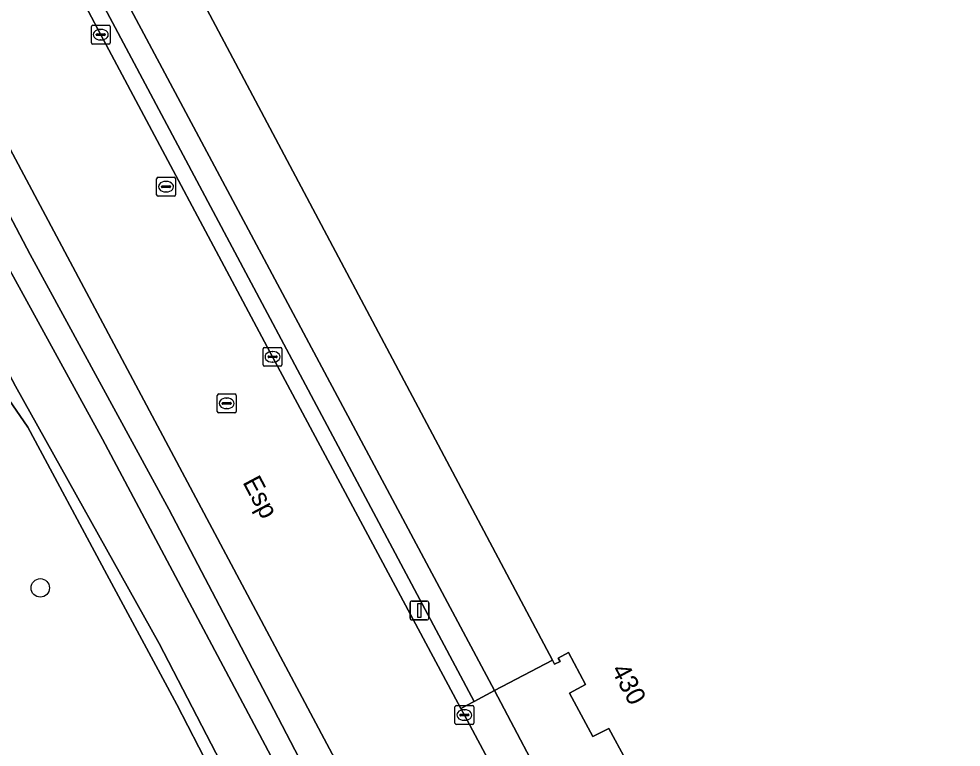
# Model space of a CAD drawing. Extents: x 161385 to 162589, y 388479 to 389756.
# Drawn here: x 161966 to 162016.1, y 388897.9 to 388936.6 of the extents above; entities that cross this region are included whole.
import ezdxf

# ---------------------------------------------------------------- set-up
doc = ezdxf.new("R2010")
doc.units = 0
for name, color, linetype in [('IMGEO_Berm_groen', 7, 'Continuous'), ('IMGEO_Boom', 7, 'Continuous'), ('IMGEO_Groenvoorziening', 7, 'Continuous'), ('IMGEO_Haag', 7, 'Continuous'), ('IMGEO_Kolk', 7, 'Continuous'), ('IMGEO_Lichtmast', 7, 'Continuous'), ('IMGEO_Oever', 7, 'Continuous'), ('IMGEO_Openbare_ruimte_label', 7, 'Continuous'), ('IMGEO_Pand', 7, 'Continuous'), ('IMGEO_Pand_nummerreeks', 7, 'Continuous'), ('IMGEO_Rijbaan_lokaal_gesloten', 7, 'Continuous'), ('IMGEO_Rioolput', 7, 'Continuous'), ('IMGEO_Voetpad_open', 7, 'Continuous'), ('IMGEO_Waterloop', 7, 'Continuous')]:
    doc.layers.add(name, color=color, linetype=linetype)

msp = doc.modelspace()

# ---------------------------------------------------------------- linework, layer by layer
at = {"layer": 'IMGEO_Berm_groen'}
for points in [[(161968.389, 388939.475), (161970.358, 388935.737), (161979.492, 388918.612), (161989.503, 388899.925), (161990.206, 388900.294), (161969.102, 388939.923)], [(162024.808, 388810.847), (162000, 388863.953), (161997.535, 388869.23), (161997.09, 388870.182), (161995.294, 388873.775), (161961.889, 388936.482)], [(161961.038, 388934.61), (161966.605, 388924.048), (161973.975, 388910.518), (161979.556, 388899.869), (161985.375, 388888.699), (161989.458, 388881.111), (161991.934, 388876.857), (161994.36, 388871.666), (161996.577, 388867.59), (161999.373, 388861.434), (162009.725, 388838.945), (162015.291, 388827.115)], [(162011.047, 388825.738), (162008.1, 388831.768), (162003.952, 388840.962), (162000.551, 388848.039), (161996.99, 388855.523), (161993.502, 388862.945), (161989.966, 388870.547), (161986.387, 388877.47), (161983.254, 388883.681), (161979.081, 388891.053), (161974.403, 388900.125), (161970.685, 388907.05), (161966.487, 388914.871), (161964.669, 388917.476)]]:
    msp.add_lwpolyline(points, dxfattribs=at)
at = {"layer": 'IMGEO_Boom'}
msp.add_circle((161967.141, 388906.331), 0.489, dxfattribs=at)
at = {"layer": 'IMGEO_Groenvoorziening'}
msp.add_lwpolyline([(161970.155, 388940.477), (161991.298, 388900.866), (161994.377, 388902.481), (161973.132, 388942.524)], dxfattribs=at)
at = {"layer": 'IMGEO_Haag'}
msp.add_lwpolyline([(161970.155, 388940.477), (161991.298, 388900.866), (161994.377, 388902.481), (161973.132, 388942.524)], dxfattribs=at)
at = {"layer": 'IMGEO_Kolk'}
for p, q in [((161969.857, 388935.312), (161969.857, 388936.164)), ((161969.932, 388936.238), (161970.784, 388936.238)), ((161970.345, 388936.018), (161970.37, 388936.018)), ((161970.858, 388936.164), (161970.858, 388935.312)), ((161970.116, 388935.732), (161970.116, 388935.744)), ((161970.554, 388935.695), (161970.156, 388935.695)), ((161970.159, 388935.781), (161970.557, 388935.781)), ((161970.6, 388935.744), (161970.6, 388935.732)), ((161970.784, 388935.238), (161969.932, 388935.238)), ((161970.368, 388935.458), (161970.343, 388935.458)), ((161978.992, 388918.186), (161978.992, 388919.038)), ((161979.067, 388919.112), (161979.919, 388919.112)), ((161979.993, 388919.038), (161979.993, 388918.186)), ((161979.251, 388918.606), (161979.251, 388918.618)), ((161979.689, 388918.569), (161979.291, 388918.569)), ((161979.294, 388918.655), (161979.692, 388918.655)), ((161979.48, 388918.892), (161979.505, 388918.892)), ((161979.735, 388918.618), (161979.735, 388918.606)), ((161979.919, 388918.112), (161979.067, 388918.112)), ((161979.503, 388918.332), (161979.478, 388918.332)), ((161989.192, 388899.146), (161989.192, 388899.998)), ((161989.267, 388900.072), (161990.119, 388900.072)), ((161990.193, 388899.998), (161990.193, 388899.146)), ((161989.451, 388899.566), (161989.451, 388899.578)), ((161989.889, 388899.529), (161989.491, 388899.529)), ((161989.494, 388899.615), (161989.892, 388899.615)), ((161989.68, 388899.852), (161989.705, 388899.852)), ((161989.935, 388899.578), (161989.935, 388899.566)), ((161990.119, 388899.072), (161989.267, 388899.072)), ((161989.703, 388899.292), (161989.678, 388899.292))]:
    msp.add_line(p, q, dxfattribs=at)
for points in [[(161969.857, 388935.312), (161969.857, 388936.164)], [(161969.932, 388936.238), (161970.784, 388936.238)], [(161970.858, 388936.164), (161970.858, 388935.312)], [(161970.784, 388935.238), (161969.932, 388935.238)], [(161978.992, 388918.186), (161978.992, 388919.038)], [(161979.067, 388919.112), (161979.919, 388919.112)], [(161979.993, 388919.038), (161979.993, 388918.186)], [(161979.919, 388918.112), (161979.067, 388918.112)], [(161989.192, 388899.146), (161989.192, 388899.998)], [(161989.267, 388900.072), (161990.119, 388900.072)], [(161990.193, 388899.998), (161990.193, 388899.146)], [(161990.119, 388899.072), (161989.267, 388899.072)]]:
    msp.add_lwpolyline(points, dxfattribs=at)
for centre, radius, start, end in [((161969.934, 388936.162), 0.0765, 91.552, 178.448), ((161969.934, 388936.162), 0.0765, 91.552, 178.448), ((161970.782, 388936.162), 0.0765, 1.552, 88.448), ((161970.782, 388936.162), 0.0765, 1.552, 88.448), ((161970.156, 388935.741), 0.0403, 85.8775, 175.7526), ((161970.153, 388935.731), 0.0366, 178.938, 274.7102), ((161970.557, 388935.738), 0.043, 264.8664, 352.4533), ((161970.561, 388935.743), 0.0386, 1.7309, 96.639), ((161969.934, 388935.314), 0.0765, 181.552, 268.448), ((161969.934, 388935.314), 0.0765, 181.552, 268.448), ((161970.782, 388935.314), 0.0765, 271.552, 358.448), ((161970.782, 388935.314), 0.0765, 271.552, 358.448), ((161979.069, 388919.036), 0.0765, 91.552, 178.448), ((161979.069, 388919.036), 0.0765, 91.552, 178.448), ((161979.917, 388919.036), 0.0765, 1.552, 88.448), ((161979.917, 388919.036), 0.0765, 1.552, 88.448), ((161979.291, 388918.615), 0.0403, 85.8775, 175.7526), ((161979.288, 388918.605), 0.0366, 178.938, 274.7102), ((161979.692, 388918.612), 0.043, 264.8664, 352.4533), ((161979.696, 388918.617), 0.0386, 1.7309, 96.639), ((161979.069, 388918.188), 0.0765, 181.552, 268.448), ((161979.069, 388918.188), 0.0765, 181.552, 268.448), ((161979.917, 388918.188), 0.0765, 271.552, 358.448), ((161979.917, 388918.188), 0.0765, 271.552, 358.448), ((161989.269, 388899.996), 0.0765, 91.552, 178.448), ((161989.269, 388899.996), 0.0765, 91.552, 178.448), ((161990.117, 388899.996), 0.0765, 1.552, 88.448), ((161990.117, 388899.996), 0.0765, 1.552, 88.448), ((161989.491, 388899.575), 0.0403, 85.8775, 175.7526), ((161989.488, 388899.565), 0.0366, 178.938, 274.7102), ((161989.892, 388899.572), 0.043, 264.8664, 352.4533), ((161989.896, 388899.577), 0.0386, 1.7309, 96.639), ((161989.269, 388899.148), 0.0765, 181.552, 268.448), ((161989.269, 388899.148), 0.0765, 181.552, 268.448), ((161990.117, 388899.148), 0.0765, 271.552, 358.448), ((161990.117, 388899.148), 0.0765, 271.552, 358.448)]:
    msp.add_arc(centre, radius, start, end, dxfattribs=at)
for centre, major_axis, ratio, start_param, end_param in [((161970.344, 388935.738), (-0.387, 0.002), 0.722429, 4.712389, 7.853982), ((161970.369, 388935.738), (-0.39, 0.002), 0.717154, 1.570796, 4.712389), ((161979.479, 388918.612), (-0.387, 0.002), 0.722429, 4.712389, 7.853982), ((161979.504, 388918.612), (-0.39, 0.002), 0.717154, 1.570796, 4.712389), ((161989.679, 388899.572), (-0.387, 0.002), 0.722429, 4.712389, 7.853982), ((161989.704, 388899.572), (-0.39, 0.002), 0.717154, 1.570796, 4.712389)]:
    msp.add_ellipse(centre, major_axis=major_axis, ratio=ratio, start_param=start_param, end_param=end_param, dxfattribs=at)
at = {"layer": 'IMGEO_Lichtmast'}
for p, q in [((161986.807, 388904.727), (161986.807, 388905.527)), ((161986.807, 388905.527), (161986.807, 388904.727)), ((161986.907, 388905.627), (161987.697, 388905.627)), ((161987.697, 388905.627), (161986.907, 388905.627)), ((161987.797, 388905.527), (161987.797, 388904.727)), ((161987.797, 388904.727), (161987.797, 388905.527)), ((161987.697, 388904.627), (161986.907, 388904.627)), ((161986.907, 388904.627), (161987.697, 388904.627))]:
    msp.add_line(p, q, dxfattribs=at)
msp.add_lwpolyline([(161987.227, 388905.502), (161987.377, 388905.502), (161987.377, 388904.752), (161987.227, 388904.752), (161987.227, 388905.502)], dxfattribs=at)
for centre, start, end in [((161986.907, 388905.527), 90, 180), ((161986.907, 388905.527), 90, 180), ((161987.697, 388905.527), 0, 90), ((161987.697, 388905.527), 360, 90), ((161986.907, 388904.727), 180, 270), ((161986.907, 388904.727), 180, 270), ((161987.697, 388904.727), 270, 0), ((161987.697, 388904.727), 270, 0)]:
    msp.add_arc(centre, 0.1, start, end, dxfattribs=at)
at = {"layer": 'IMGEO_Oever'}
for points in [[(162057.6, 388706.607), (162048.463, 388732.272), (162043.653, 388745.629), (162037.763, 388760.637), (162034.255, 388770.348), (162029.937, 388781.916), (162028.763, 388785.061), (162028.09, 388786.865), (162022.898, 388799.997), (162017.299, 388813.29), (162011.729, 388825.521), (161997.026, 388856.73), (161992.962, 388865.623), (161985.653, 388880.171), (161979.241, 388892.222), (161973.46, 388903.38), (161965.825, 388917.051), (161959.219, 388929.478), (161955.4, 388937.311), (161945.813, 388954.71), (161943.053, 388960.238), (161942.447, 388962.063), (161941.837, 388963.119), (161941.224, 388963.683)], [(162015.291, 388827.115), (162009.725, 388838.945), (161999.373, 388861.434), (161996.577, 388867.59), (161994.36, 388871.666), (161991.934, 388876.857), (161989.458, 388881.111), (161985.375, 388888.699), (161979.556, 388899.869), (161973.975, 388910.518), (161966.605, 388924.048), (161961.038, 388934.61)], [(161962.678, 388928.366), (161970.452, 388914.234), (161989.402, 388878.601), (161994.658, 388868.229), (161999.307, 388858.055), (162007.133, 388841.446), (162009.798, 388836.706), (162010.967, 388833.651), (162012.265, 388830.652), (162012.581, 388830.206), (162020.661, 388813.167)], [(161964.669, 388917.476), (161966.487, 388914.871), (161970.685, 388907.05), (161974.403, 388900.125), (161979.081, 388891.053), (161983.254, 388883.681), (161986.387, 388877.47), (161989.966, 388870.547), (161993.502, 388862.945), (161996.99, 388855.523), (162000.551, 388848.039), (162003.952, 388840.962), (162008.1, 388831.768), (162011.047, 388825.738)]]:
    msp.add_lwpolyline(points, dxfattribs=at)
at = {"layer": 'IMGEO_Pand'}
msp.add_lwpolyline([(161973.132, 388942.524), (161994.377, 388902.481), (161994.489, 388902.269), (161994.781, 388902.424), (161994.687, 388902.601), (161995.235, 388902.891), (161996.136, 388901.195), (161995.281, 388900.739), (161996.517, 388898.421), (161997.381, 388898.862), (161998.275, 388897.186)], dxfattribs=at)
at = {"layer": 'IMGEO_Rijbaan_lokaal_gesloten'}
for points in [[(161992.639, 388894.058), (161989.692, 388899.572), (161989.503, 388899.925), (161979.492, 388918.612), (161970.358, 388935.737), (161968.389, 388939.475)], [(161961.889, 388936.482), (161995.294, 388873.775), (161997.09, 388870.182), (161997.535, 388869.23), (162000, 388863.953), (162024.808, 388810.847)]]:
    msp.add_lwpolyline(points, dxfattribs=at)
at = {"layer": 'IMGEO_Rioolput'}
for p, q in [((161973.328, 388927.23), (161973.328, 388928.082)), ((161973.403, 388928.156), (161974.255, 388928.156)), ((161974.329, 388928.082), (161974.329, 388927.23)), ((161973.587, 388927.65), (161973.587, 388927.662)), ((161974.025, 388927.613), (161973.627, 388927.613)), ((161973.63, 388927.699), (161974.028, 388927.699)), ((161973.816, 388927.936), (161973.841, 388927.936)), ((161974.071, 388927.662), (161974.071, 388927.65)), ((161974.255, 388927.156), (161973.403, 388927.156)), ((161973.839, 388927.376), (161973.814, 388927.376)), ((161976.553, 388915.712), (161976.553, 388916.564)), ((161976.628, 388916.638), (161977.48, 388916.638)), ((161977.554, 388916.564), (161977.554, 388915.712)), ((161976.812, 388916.132), (161976.812, 388916.144)), ((161977.25, 388916.095), (161976.852, 388916.095)), ((161976.855, 388916.181), (161977.253, 388916.181)), ((161977.041, 388916.418), (161977.066, 388916.418)), ((161977.296, 388916.144), (161977.296, 388916.132)), ((161977.48, 388915.638), (161976.628, 388915.638)), ((161977.064, 388915.858), (161977.039, 388915.858))]:
    msp.add_line(p, q, dxfattribs=at)
for points in [[(161973.328, 388927.23), (161973.328, 388928.082)], [(161973.403, 388928.156), (161974.255, 388928.156)], [(161974.329, 388928.082), (161974.329, 388927.23)], [(161974.255, 388927.156), (161973.403, 388927.156)], [(161976.553, 388915.712), (161976.553, 388916.564)], [(161976.628, 388916.638), (161977.48, 388916.638)], [(161977.554, 388916.564), (161977.554, 388915.712)], [(161977.48, 388915.638), (161976.628, 388915.638)]]:
    msp.add_lwpolyline(points, dxfattribs=at)
for centre, radius, start, end in [((161973.405, 388928.08), 0.0765, 91.552, 178.448), ((161973.405, 388928.08), 0.0765, 91.552, 178.448), ((161974.253, 388928.08), 0.0765, 1.552, 88.448), ((161974.253, 388928.08), 0.0765, 1.552, 88.448), ((161973.627, 388927.659), 0.0403, 85.8775, 175.7526), ((161973.624, 388927.649), 0.0366, 178.938, 274.7102), ((161974.028, 388927.656), 0.043, 264.8664, 352.4533), ((161974.032, 388927.661), 0.0386, 1.7309, 96.639), ((161973.405, 388927.232), 0.0765, 181.552, 268.448), ((161973.405, 388927.232), 0.0765, 181.552, 268.448), ((161974.253, 388927.232), 0.0765, 271.552, 358.448), ((161974.253, 388927.232), 0.0765, 271.552, 358.448), ((161976.63, 388916.562), 0.0765, 91.552, 178.448), ((161976.63, 388916.562), 0.0765, 91.552, 178.448), ((161977.478, 388916.562), 0.0765, 1.552, 88.448), ((161977.478, 388916.562), 0.0765, 1.552, 88.448), ((161976.852, 388916.141), 0.0403, 85.8775, 175.7526), ((161976.849, 388916.131), 0.0366, 178.938, 274.7102), ((161977.253, 388916.138), 0.043, 264.8664, 352.4533), ((161977.257, 388916.143), 0.0386, 1.7309, 96.639), ((161976.63, 388915.714), 0.0765, 181.552, 268.448), ((161976.63, 388915.714), 0.0765, 181.552, 268.448), ((161977.478, 388915.714), 0.0765, 271.552, 358.448), ((161977.478, 388915.714), 0.0765, 271.552, 358.448)]:
    msp.add_arc(centre, radius, start, end, dxfattribs=at)
for centre, major_axis, ratio, start_param, end_param in [((161973.815, 388927.656), (-0.387, 0.002), 0.722429, 4.712389, 7.853982), ((161973.84, 388927.656), (-0.39, 0.002), 0.717154, 1.570796, 4.712389), ((161977.04, 388916.138), (-0.387, 0.002), 0.722429, 4.712389, 7.853982), ((161977.065, 388916.138), (-0.39, 0.002), 0.717154, 1.570796, 4.712389)]:
    msp.add_ellipse(centre, major_axis=major_axis, ratio=ratio, start_param=start_param, end_param=end_param, dxfattribs=at)
at = {"layer": 'IMGEO_Voetpad_open'}
for points in [[(161991.298, 388900.866), (161970.155, 388940.477), (161969.102, 388939.923), (161990.206, 388900.294)], [(161994.39, 388894.985), (161997.547, 388896.655), (161997.395, 388896.945), (161997.634, 388897.072), (161997.728, 388896.895), (161998.275, 388897.186), (161997.381, 388898.862), (161996.517, 388898.421), (161995.281, 388900.739), (161996.136, 388901.195), (161995.235, 388902.891), (161994.687, 388902.601), (161994.781, 388902.424), (161994.489, 388902.269), (161994.377, 388902.481), (161991.298, 388900.866)], [(161991.298, 388900.866), (161990.206, 388900.294), (161989.503, 388899.925), (161989.692, 388899.572), (161992.639, 388894.058), (161993.345, 388894.432), (161994.39, 388894.985)]]:
    msp.add_lwpolyline(points, close=True, dxfattribs=at)
at = {"layer": 'IMGEO_Waterloop'}
for points in [[(161942.882, 388963.862), (161941.837, 388963.119), (161942.447, 388962.063), (161943.053, 388960.238), (161945.813, 388954.71), (161955.4, 388937.311), (161959.219, 388929.478), (161965.825, 388917.051), (161973.46, 388903.38), (161979.241, 388892.222), (161985.653, 388880.171), (161992.962, 388865.623), (161997.026, 388856.73), (162011.729, 388825.521)], [(162020.661, 388813.167), (162012.581, 388830.206), (162012.265, 388830.652), (162010.967, 388833.651), (162009.798, 388836.706), (162007.133, 388841.446), (161999.307, 388858.055), (161994.658, 388868.229), (161989.402, 388878.601), (161970.452, 388914.234), (161962.678, 388928.366)]]:
    msp.add_lwpolyline(points, dxfattribs=at)

# ---------------------------------------------------------------- texts
at = {"layer": 'IMGEO_Openbare_ruimte_label'}
msp.add_text('Esp', height=1, rotation=298.0253, dxfattribs=at).set_placement((161977.881, 388911.949))
at = {"layer": 'IMGEO_Pand_nummerreeks'}
msp.add_text('430', height=1, rotation=298.069, dxfattribs=at).set_placement((161997.477, 388901.976))

doc.saveas('drawing.dxf')
